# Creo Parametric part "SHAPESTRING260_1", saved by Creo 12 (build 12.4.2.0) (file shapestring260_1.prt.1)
Units: Custom; MM, KILOGRAM, SECS

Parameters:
  PTC_WM_ITERATION = "0"
  PTC_WM_VERSION = "-.0"
  PTC_WM_LIFECYCLE_STATE = "In Work"
  PTC_WM_LIFECYCLE = "MO_CADDocument"
  PTC_WM_CREATED_BY = "Maximilian Roepper (Z0017RMS: MO)"
  PTC_WM_CREATED_ON = "18-Sep-26 11:36:42 AM"
  PTC_WM_MODIFIED_BY = "Maximilian Roepper (Z0017RMS: MO)"
  PTC_WM_MODIFIED_ON = "18-Sep-26 11:36:46 AM"
  PDMLINKNUMBER = "PDM000071455066"
  PTC_WM_NAME = "shapestring260_1.prt"
  PTC_WM_NUMBER = "PDM000071455066"

Other parameters: WEIGHT, WEIGHT_FACTOR, WEIGHT_ADD, _MASS_TEMP, _DIFF_TEMP, MC_ERRORS, SUPPLIER

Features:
  1. coordinate system
  2. datum plane "PRT_YZ"
  3. datum plane "PRT_XY"
  4. datum plane "PRT_XZ"
  5. coordinate system
  6. datum axis
  7. datum axis
  8. datum axis
  9. coordinate system
  10. imported feature
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
Other named items: PRT, SIEMENS_MO, DRW_VIEW_ORG, PRT_X, PRT_Y, PRT_Z, CS0, ROUGH_GROB

Layers: 00_STD_CSYS-KSYS, 01_STD_PLANES-EBENEN, 02_STD_AXES-ACHSEN, 03_STD_CSYS-KSYS, 24_IMPORT_FEAT-IMPORT_KE, WHITE

Surfaces: 1 plane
